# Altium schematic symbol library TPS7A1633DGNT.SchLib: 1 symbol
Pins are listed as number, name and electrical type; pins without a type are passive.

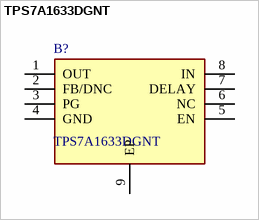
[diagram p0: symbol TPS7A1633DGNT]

## TPS7A1633DGNT
designator B?
Texas Instruments TPS7A1633DGNT, LDO Voltage Regulator, 100mA, 3.3 V +/-2%, 3  60 Vin, 8-Pin MSOP; Geometry.Height: 1.1mm
footprint SOP65P490X110-9N
pins: 1 OUT, 2 FB/DNC, 3 PG, 4 GND, 5 EN, 6 NC, 7 DELAY, 8 IN, 9 EP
